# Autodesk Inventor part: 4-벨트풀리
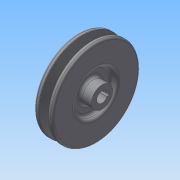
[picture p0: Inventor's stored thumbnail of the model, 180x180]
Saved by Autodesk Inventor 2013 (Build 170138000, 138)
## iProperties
Created: 2015-02
Part Number: 4-벨트풀리
Material: 일반
Document SubType Name: Modeling
Designer: Administrator
Density: 1 g/cm^3
Author: Administrator
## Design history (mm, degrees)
sketch "스케치1"
  geometry: L1 (0, 0)-(25, 0); L2 (0, 0)-(0, 11); L3 (0, 11)-(6, 11); L4 (6, 11)-(6, 21.5); L5 (6, 21.5)-(0, 21.5); L6 (0, 21.5)-(0, 45.2); L7 (0, 45.2)-(4.675, 45.2); L8 (4.675, 45.2)-(8.038, 34.2); L9 (8.038, 34.2)-(10.962, 34.2); L10 (10.962, 34.2)-(14.325, 45.2); L11 (14.325, 45.2)-(19, 45.2); L12 (19, 45.2)-(19, 21.5); L13 (19, 21.5)-(13, 21.5); L14 (13, 21.5)-(13, 11); L15 (13, 11)-(25, 11); L16 (25, 11)-(25, 0); 2 further points
  constraints: 32 end point, 9 parallel, 6 collinear, 3 equal length, 2 perpendicular, 2 point on line, 1 horizontal, 1 horizontal alignment
  dimensions: "d0" = 25 distance of L1.start L1.end; "d1" = 43 diameter of L5 L1; "d2" = 6 distance of L2.end L3.end; "d3" = 19 distance between parallel lines of L12 L6; "d4" = 34 deg angle of L10 L8; "d5" = 2.7 distance from line of point (5.5, 42.5) L7; "d6" = 8.3 distance from line of L9 point (5.5, 42.5); "d7" = 8 distance of point (13.5, 42.5) point (5.5, 42.5); "d8" = 22 diameter of L15 L1; "d9" = 85 diameter of point (5.5, 42.5) L1
revolve "회전1" sketch "스케치1" stored, may be unused: angle "d10" = 90 deg
sketch "스케치2"
  geometry: L1 (-2, 5.123)-(-2, 7.3); L2 (-2, 7.3)-(2, 7.3); L3 (2, 7.3)-(2, 5.123); C1 r 11 at (0, 0) reference; A1 r 5.5 centre (0, 0) between (-2, 5.123) and (2, 5.123); 1 further point
  constraints: 6 end point, 2 point on circle, 1 centre point, 1 coincident, 1 midpoint, 1 parallel, 1 perpendicular, 1 vertical, 1 vertical alignment
  dimensions: "d11" = 4 distance of L1.end L2.end; "d13" = 12.8 dimension on A1 L2; "d14" = 11 diameter of A1
extrude "돌출1" cut sketch "스케치2" stored distance "d15" = 10; taper "d16" = 0 deg
fillet "모깎기1" dims "d17" = 2, "d18" = 0.5, "d19" = 1, "d20" = 3
node "솔리드1"
